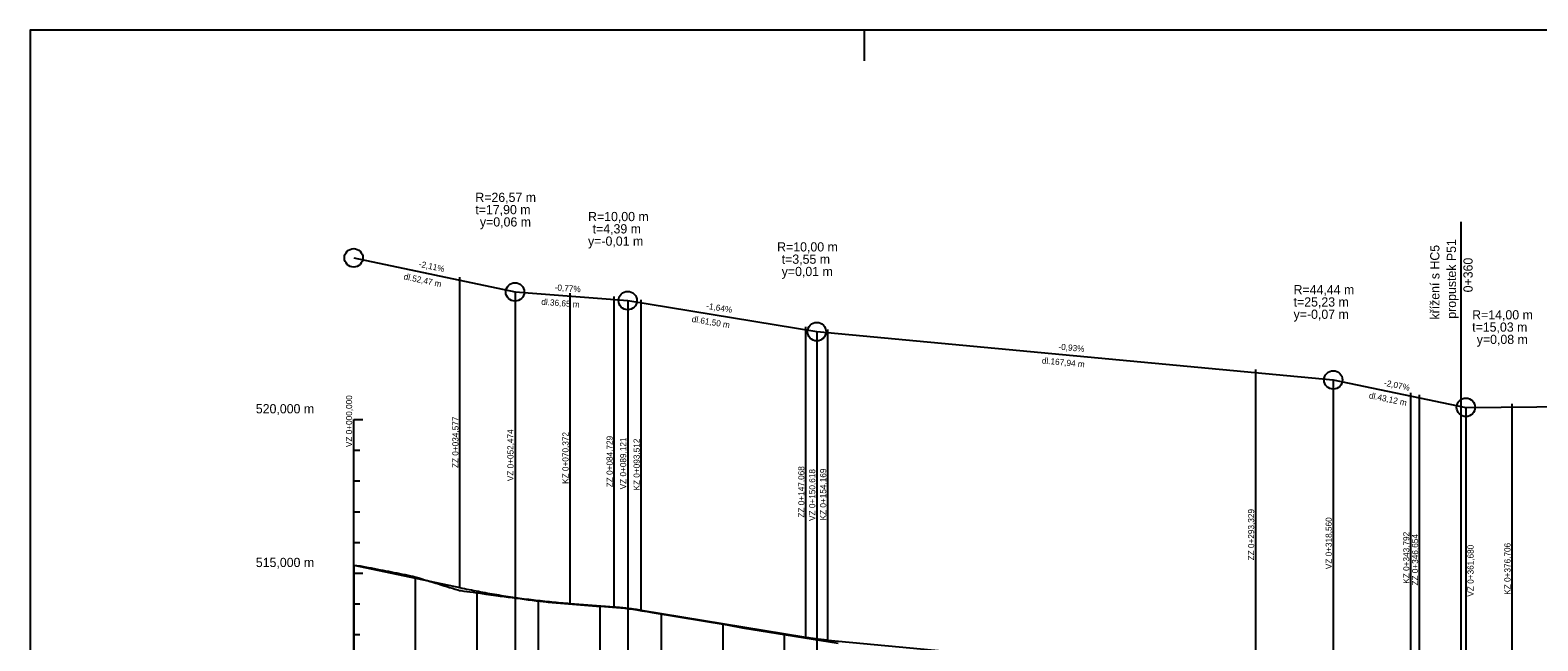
# Model space of a CAD drawing. Extents: x -632716 to -629545, y -1094726 to -1088285.
# Drawn here: x -632716 to -632225.7, y -1093293.8 to -1093095.1 of the extents above; entities that cross this region are included whole.
import ezdxf

# ---------------------------------------------------------------- set-up
doc = ezdxf.new("R2010")
doc.units = 0
for name, color, linetype in [('20', 7, 'Continuous'), ('Default', 7, 'Continuous'), ('formát', 7, 'Continuous'), ('REZ_POPIS', 7, 'Continuous'), ('REZ_TENKA', 7, 'Continuous'), ('REZ_TLUSTA', 7, 'Continuous'), ('SKLONY_NIVELETA', 7, 'Continuous'), ('SKLONY_POPIS', 7, 'Continuous'), ('TECNY_NIVELETA', 7, 'Continuous'), ('VOZOVKA', 7, 'Continuous')]:
    doc.layers.add(name, color=color, linetype=linetype)

msp = doc.modelspace()

# ---------------------------------------------------------------- linework, layer by layer
at = {"layer": '20'}
for points in [[(-632610.75, -1093269.14), (-632610.75, -1093521.74), (-632610.75, -1093571.74), (-632610.75, -1093511.74)], [(-632590.75, -1093273.37), (-632590.75, -1093521.74), (-632590.75, -1093571.74), (-632590.75, -1093511.74)], [(-632570.75, -1093277.54), (-632570.75, -1093521.74), (-632570.75, -1093571.74), (-632570.75, -1093511.74)], [(-632550.75, -1093280.6), (-632550.75, -1093521.74), (-632550.75, -1093571.74), (-632550.75, -1093511.74)], [(-632530.75, -1093282.34), (-632530.75, -1093521.74), (-632530.75, -1093571.74), (-632530.75, -1093511.74)], [(-632510.75, -1093284.83), (-632510.75, -1093521.74), (-632510.75, -1093571.74), (-632510.75, -1093511.74)], [(-632490.75, -1093288.12), (-632490.75, -1093521.74), (-632490.75, -1093571.74), (-632490.75, -1093511.74)], [(-632470.75, -1093291.41), (-632470.75, -1093521.74), (-632470.75, -1093571.74), (-632470.75, -1093511.74)]]:
    msp.add_lwpolyline(points, dxfattribs=at)
at = {"layer": 'Default'}
for p, q in [((-632610.75, -1093269.14), (-632576.18, -1093276.45)), ((-632610.75, -1093269.14), (-632576.18, -1093276.45)), ((-632540.38, -1093281.6), (-632526.02, -1093282.7)), ((-632540.38, -1093281.6), (-632526.02, -1093282.7)), ((-632517.24, -1093283.76), (-632463.69, -1093292.57)), ((-632517.24, -1093283.76), (-632463.69, -1093292.57)), ((-632456.58, -1093293.49), (-632317.42, -1093306.49)), ((-632456.58, -1093293.49), (-632317.42, -1093306.49))]:
    msp.add_line(p, q, dxfattribs=at)
for points in [[(-632576.18, -1093276.45), (-632575.43, -1093276.6), (-632574.69, -1093276.76), (-632573.94, -1093276.91), (-632573.19, -1093277.06), (-632572.45, -1093277.21), (-632571.7, -1093277.35), (-632570.96, -1093277.5), (-632570.21, -1093277.64), (-632569.46, -1093277.78), (-632568.72, -1093277.92), (-632567.97, -1093278.05), (-632567.23, -1093278.19), (-632566.48, -1093278.32), (-632565.74, -1093278.45), (-632564.99, -1093278.58), (-632564.24, -1093278.7), (-632563.5, -1093278.82), (-632562.75, -1093278.95), (-632562.01, -1093279.06), (-632561.26, -1093279.18), (-632560.52, -1093279.3), (-632559.77, -1093279.41), (-632559.02, -1093279.52), (-632557.53, -1093279.73), (-632556.79, -1093279.84), (-632556.04, -1093279.94), (-632555.3, -1093280.04), (-632554.55, -1093280.14), (-632553.8, -1093280.23), (-632553.06, -1093280.33), (-632552.31, -1093280.42), (-632551.57, -1093280.51), (-632550.82, -1093280.6), (-632550.08, -1093280.68), (-632549.33, -1093280.77), (-632548.58, -1093280.85), (-632547.84, -1093280.93), (-632547.09, -1093281), (-632546.35, -1093281.08), (-632545.6, -1093281.15), (-632544.86, -1093281.22), (-632544.11, -1093281.29), (-632543.36, -1093281.36), (-632542.62, -1093281.42), (-632541.87, -1093281.48), (-632541.13, -1093281.54), (-632540.38, -1093281.6)], [(-632576.18, -1093276.45), (-632575.43, -1093276.6), (-632574.69, -1093276.76), (-632573.94, -1093276.91), (-632573.19, -1093277.06), (-632572.45, -1093277.21), (-632571.7, -1093277.35), (-632570.96, -1093277.5), (-632570.21, -1093277.64), (-632569.46, -1093277.78), (-632568.72, -1093277.92), (-632567.97, -1093278.05), (-632567.23, -1093278.19), (-632566.48, -1093278.32), (-632565.74, -1093278.45), (-632564.99, -1093278.58), (-632564.24, -1093278.7), (-632563.5, -1093278.82), (-632562.75, -1093278.95), (-632562.01, -1093279.06), (-632561.26, -1093279.18), (-632560.52, -1093279.3), (-632559.77, -1093279.41), (-632559.02, -1093279.52), (-632557.53, -1093279.73), (-632556.79, -1093279.84), (-632556.04, -1093279.94), (-632555.3, -1093280.04), (-632554.55, -1093280.14), (-632553.8, -1093280.23), (-632553.06, -1093280.33), (-632552.31, -1093280.42), (-632551.57, -1093280.51), (-632550.82, -1093280.6), (-632550.08, -1093280.68), (-632549.33, -1093280.77), (-632548.58, -1093280.85), (-632547.84, -1093280.93), (-632547.09, -1093281), (-632546.35, -1093281.08), (-632545.6, -1093281.15), (-632544.86, -1093281.22), (-632544.11, -1093281.29), (-632543.36, -1093281.36), (-632542.62, -1093281.42), (-632541.87, -1093281.48), (-632541.13, -1093281.54), (-632540.38, -1093281.6)], [(-632526.02, -1093282.7), (-632525.84, -1093282.72), (-632525.66, -1093282.73), (-632525.48, -1093282.75), (-632525.29, -1093282.76), (-632525.11, -1093282.78), (-632524.93, -1093282.79), (-632524.74, -1093282.81), (-632524.56, -1093282.83), (-632524.38, -1093282.84), (-632524.19, -1093282.86), (-632524.01, -1093282.88), (-632523.83, -1093282.9), (-632523.65, -1093282.91), (-632523.46, -1093282.93), (-632523.28, -1093282.95), (-632523.1, -1093282.97), (-632522.91, -1093282.99), (-632522.73, -1093283.01), (-632522.55, -1093283.03), (-632522.36, -1093283.05), (-632522.18, -1093283.07), (-632522, -1093283.09), (-632521.82, -1093283.11), (-632521.45, -1093283.16), (-632521.27, -1093283.18), (-632521.08, -1093283.2), (-632520.9, -1093283.23), (-632520.72, -1093283.25), (-632520.54, -1093283.27), (-632520.35, -1093283.3), (-632520.17, -1093283.32), (-632519.99, -1093283.35), (-632519.8, -1093283.37), (-632519.62, -1093283.4), (-632519.44, -1093283.42), (-632519.25, -1093283.45), (-632519.07, -1093283.48), (-632518.89, -1093283.5), (-632518.71, -1093283.53), (-632518.52, -1093283.56), (-632518.34, -1093283.59), (-632518.16, -1093283.62), (-632517.97, -1093283.64), (-632517.79, -1093283.67), (-632517.61, -1093283.7), (-632517.42, -1093283.73), (-632517.24, -1093283.76)], [(-632526.02, -1093282.7), (-632525.84, -1093282.72), (-632525.66, -1093282.73), (-632525.48, -1093282.75), (-632525.29, -1093282.76), (-632525.11, -1093282.78), (-632524.93, -1093282.79), (-632524.74, -1093282.81), (-632524.56, -1093282.83), (-632524.38, -1093282.84), (-632524.19, -1093282.86), (-632524.01, -1093282.88), (-632523.83, -1093282.9), (-632523.65, -1093282.91), (-632523.46, -1093282.93), (-632523.28, -1093282.95), (-632523.1, -1093282.97), (-632522.91, -1093282.99), (-632522.73, -1093283.01), (-632522.55, -1093283.03), (-632522.36, -1093283.05), (-632522.18, -1093283.07), (-632522, -1093283.09), (-632521.82, -1093283.11), (-632521.45, -1093283.16), (-632521.27, -1093283.18), (-632521.08, -1093283.2), (-632520.9, -1093283.23), (-632520.72, -1093283.25), (-632520.54, -1093283.27), (-632520.35, -1093283.3), (-632520.17, -1093283.32), (-632519.99, -1093283.35), (-632519.8, -1093283.37), (-632519.62, -1093283.4), (-632519.44, -1093283.42), (-632519.25, -1093283.45), (-632519.07, -1093283.48), (-632518.89, -1093283.5), (-632518.71, -1093283.53), (-632518.52, -1093283.56), (-632518.34, -1093283.59), (-632518.16, -1093283.62), (-632517.97, -1093283.64), (-632517.79, -1093283.67), (-632517.61, -1093283.7), (-632517.42, -1093283.73), (-632517.24, -1093283.76)], [(-632463.69, -1093292.57), (-632463.54, -1093292.6), (-632463.39, -1093292.62), (-632463.24, -1093292.64), (-632463.09, -1093292.67), (-632462.95, -1093292.69), (-632462.8, -1093292.71), (-632462.65, -1093292.74), (-632462.5, -1093292.76), (-632462.35, -1093292.78), (-632462.21, -1093292.8), (-632462.06, -1093292.83), (-632461.91, -1093292.85), (-632461.76, -1093292.87), (-632461.61, -1093292.89), (-632461.47, -1093292.91), (-632461.32, -1093292.93), (-632461.17, -1093292.95), (-632461.02, -1093292.97), (-632460.87, -1093292.99), (-632460.73, -1093293.01), (-632460.58, -1093293.03), (-632460.43, -1093293.05), (-632460.28, -1093293.07), (-632459.99, -1093293.11), (-632459.84, -1093293.13), (-632459.69, -1093293.15), (-632459.54, -1093293.17), (-632459.4, -1093293.18), (-632459.25, -1093293.2), (-632459.1, -1093293.22), (-632458.95, -1093293.24), (-632458.8, -1093293.25), (-632458.66, -1093293.27), (-632458.51, -1093293.29), (-632458.36, -1093293.31), (-632458.21, -1093293.32), (-632458.06, -1093293.34), (-632457.92, -1093293.35), (-632457.77, -1093293.37), (-632457.62, -1093293.38), (-632457.47, -1093293.4), (-632457.32, -1093293.41), (-632457.18, -1093293.43), (-632457.03, -1093293.44), (-632456.88, -1093293.46), (-632456.73, -1093293.47), (-632456.58, -1093293.49)], [(-632463.69, -1093292.57), (-632463.54, -1093292.6), (-632463.39, -1093292.62), (-632463.24, -1093292.64), (-632463.09, -1093292.67), (-632462.95, -1093292.69), (-632462.8, -1093292.71), (-632462.65, -1093292.74), (-632462.5, -1093292.76), (-632462.35, -1093292.78), (-632462.21, -1093292.8), (-632462.06, -1093292.83), (-632461.91, -1093292.85), (-632461.76, -1093292.87), (-632461.61, -1093292.89), (-632461.47, -1093292.91), (-632461.32, -1093292.93), (-632461.17, -1093292.95), (-632461.02, -1093292.97), (-632460.87, -1093292.99), (-632460.73, -1093293.01), (-632460.58, -1093293.03), (-632460.43, -1093293.05), (-632460.28, -1093293.07), (-632459.99, -1093293.11), (-632459.84, -1093293.13), (-632459.69, -1093293.15), (-632459.54, -1093293.17), (-632459.4, -1093293.18), (-632459.25, -1093293.2), (-632459.1, -1093293.22), (-632458.95, -1093293.24), (-632458.8, -1093293.25), (-632458.66, -1093293.27), (-632458.51, -1093293.29), (-632458.36, -1093293.31), (-632458.21, -1093293.32), (-632458.06, -1093293.34), (-632457.92, -1093293.35), (-632457.77, -1093293.37), (-632457.62, -1093293.38), (-632457.47, -1093293.4), (-632457.32, -1093293.41), (-632457.18, -1093293.43), (-632457.03, -1093293.44), (-632456.88, -1093293.46), (-632456.73, -1093293.47), (-632456.58, -1093293.49)]]:
    msp.add_lwpolyline(points, dxfattribs=at)
at = {"layer": 'formát'}
msp.add_line((-632444.61, -1093105.05), (-632444.61, -1093095.05), dxfattribs=at)
msp.add_lwpolyline([(-632715.96, -1093689.05), (-630764.61, -1093689.05), (-630764.61, -1093095.05), (-632715.96, -1093095.05)], close=True, dxfattribs=at)
at = {"layer": 'REZ_TENKA'}
for p, q in [((-632610.75, -1093571.74), (-632610.75, -1093221.74)), ((-632610.75, -1093231.74), (-632608.75, -1093231.74)), ((-632610.75, -1093241.74), (-632608.75, -1093241.74)), ((-632610.75, -1093251.74), (-632608.75, -1093251.74)), ((-632610.75, -1093261.74), (-632608.75, -1093261.74)), ((-632610.75, -1093281.74), (-632608.75, -1093281.74)), ((-632610.75, -1093291.74), (-632608.75, -1093291.74))]:
    msp.add_line(p, q, dxfattribs=at)
at = {"layer": 'REZ_TLUSTA'}
for p, q in [((-632610.75, -1093221.74), (-632607.75, -1093221.74)), ((-632610.75, -1093221.74), (-632607.75, -1093221.74)), ((-632610.75, -1093271.74), (-632607.75, -1093271.74))]:
    msp.add_line(p, q, dxfattribs=at)
at = {"layer": 'SKLONY_NIVELETA'}
for p, q in [((-632250.75, -1093157.4), (-632250.75, -1093316.8)), ((-632610.75, -1093169.14), (-632610.75, -1093169.14)), ((-632610.75, -1093169.14), (-632558.28, -1093180.23)), ((-632558.28, -1093180.23), (-632558.28, -1093571.74)), ((-632558.28, -1093180.23), (-632521.63, -1093183.04)), ((-632521.63, -1093183.04), (-632521.63, -1093571.74)), ((-632521.63, -1093183.04), (-632460.14, -1093193.15)), ((-632460.14, -1093193.15), (-632460.14, -1093571.74)), ((-632460.14, -1093193.15), (-632292.19, -1093208.85)), ((-632292.19, -1093208.85), (-632292.19, -1093571.74)), ((-632292.19, -1093208.85), (-632249.07, -1093217.78)), ((-632249.07, -1093217.78), (-632179.54, -1093217.25)), ((-632249.07, -1093217.78), (-632249.07, -1093571.74)), ((-632610.75, -1093269.14), (-632576.18, -1093276.45)), ((-632540.38, -1093281.6), (-632526.02, -1093282.7)), ((-632517.24, -1093283.76), (-632463.69, -1093292.57)), ((-632456.58, -1093293.49), (-632317.42, -1093306.49))]:
    msp.add_line(p, q, dxfattribs=at)
for points in [[(-632576.18, -1093276.45), (-632575.43, -1093276.6), (-632574.69, -1093276.76), (-632573.94, -1093276.91), (-632573.19, -1093277.06), (-632572.45, -1093277.21), (-632571.7, -1093277.35), (-632570.96, -1093277.5), (-632570.21, -1093277.64), (-632569.46, -1093277.78), (-632568.72, -1093277.92), (-632567.97, -1093278.05), (-632567.23, -1093278.19), (-632566.48, -1093278.32), (-632565.74, -1093278.45), (-632564.99, -1093278.58), (-632564.24, -1093278.7), (-632563.5, -1093278.82), (-632562.75, -1093278.95), (-632562.01, -1093279.06), (-632561.26, -1093279.18), (-632560.52, -1093279.3), (-632559.77, -1093279.41), (-632559.02, -1093279.52), (-632557.53, -1093279.73), (-632556.79, -1093279.84), (-632556.04, -1093279.94), (-632555.3, -1093280.04), (-632554.55, -1093280.14), (-632553.8, -1093280.23), (-632553.06, -1093280.33), (-632552.31, -1093280.42), (-632551.57, -1093280.51), (-632550.82, -1093280.6), (-632550.08, -1093280.68), (-632549.33, -1093280.77), (-632548.58, -1093280.85), (-632547.84, -1093280.93), (-632547.09, -1093281), (-632546.35, -1093281.08), (-632545.6, -1093281.15), (-632544.86, -1093281.22), (-632544.11, -1093281.29), (-632543.36, -1093281.36), (-632542.62, -1093281.42), (-632541.87, -1093281.48), (-632541.13, -1093281.54), (-632540.38, -1093281.6)], [(-632526.02, -1093282.7), (-632525.84, -1093282.72), (-632525.66, -1093282.73), (-632525.48, -1093282.75), (-632525.29, -1093282.76), (-632525.11, -1093282.78), (-632524.93, -1093282.79), (-632524.74, -1093282.81), (-632524.56, -1093282.83), (-632524.38, -1093282.84), (-632524.19, -1093282.86), (-632524.01, -1093282.88), (-632523.83, -1093282.9), (-632523.65, -1093282.91), (-632523.46, -1093282.93), (-632523.28, -1093282.95), (-632523.1, -1093282.97), (-632522.91, -1093282.99), (-632522.73, -1093283.01), (-632522.55, -1093283.03), (-632522.36, -1093283.05), (-632522.18, -1093283.07), (-632522, -1093283.09), (-632521.82, -1093283.11), (-632521.45, -1093283.16), (-632521.27, -1093283.18), (-632521.08, -1093283.2), (-632520.9, -1093283.23), (-632520.72, -1093283.25), (-632520.54, -1093283.27), (-632520.35, -1093283.3), (-632520.17, -1093283.32), (-632519.99, -1093283.35), (-632519.8, -1093283.37), (-632519.62, -1093283.4), (-632519.44, -1093283.42), (-632519.25, -1093283.45), (-632519.07, -1093283.48), (-632518.89, -1093283.5), (-632518.71, -1093283.53), (-632518.52, -1093283.56), (-632518.34, -1093283.59), (-632518.16, -1093283.62), (-632517.97, -1093283.64), (-632517.79, -1093283.67), (-632517.61, -1093283.7), (-632517.42, -1093283.73), (-632517.24, -1093283.76)], [(-632463.69, -1093292.57), (-632463.54, -1093292.6), (-632463.39, -1093292.62), (-632463.24, -1093292.64), (-632463.09, -1093292.67), (-632462.95, -1093292.69), (-632462.8, -1093292.71), (-632462.65, -1093292.74), (-632462.5, -1093292.76), (-632462.35, -1093292.78), (-632462.21, -1093292.8), (-632462.06, -1093292.83), (-632461.91, -1093292.85), (-632461.76, -1093292.87), (-632461.61, -1093292.89), (-632461.47, -1093292.91), (-632461.32, -1093292.93), (-632461.17, -1093292.95), (-632461.02, -1093292.97), (-632460.87, -1093292.99), (-632460.73, -1093293.01), (-632460.58, -1093293.03), (-632460.43, -1093293.05), (-632460.28, -1093293.07), (-632459.99, -1093293.11), (-632459.84, -1093293.13), (-632459.69, -1093293.15), (-632459.54, -1093293.17), (-632459.4, -1093293.18), (-632459.25, -1093293.2), (-632459.1, -1093293.22), (-632458.95, -1093293.24), (-632458.8, -1093293.25), (-632458.66, -1093293.27), (-632458.51, -1093293.29), (-632458.36, -1093293.31), (-632458.21, -1093293.32), (-632458.06, -1093293.34), (-632457.92, -1093293.35), (-632457.77, -1093293.37), (-632457.62, -1093293.38), (-632457.47, -1093293.4), (-632457.32, -1093293.41), (-632457.18, -1093293.43), (-632457.03, -1093293.44), (-632456.88, -1093293.46), (-632456.73, -1093293.47), (-632456.58, -1093293.49)]]:
    msp.add_lwpolyline(points, dxfattribs=at)
for centre in [(-632610.75, -1093169.14), (-632558.28, -1093180.23), (-632521.63, -1093183.04), (-632460.14, -1093193.15), (-632292.19, -1093208.85), (-632249.07, -1093217.78)]:
    msp.add_circle(centre, 3, dxfattribs=at)
at = {"layer": 'TECNY_NIVELETA'}
for p, q in [((-632610.75, -1093169.14), (-632610.75, -1093169.14)), ((-632576.18, -1093276.45), (-632576.18, -1093175.45)), ((-632558.28, -1093180.23), (-632558.28, -1093180.23)), ((-632540.38, -1093281.6), (-632540.38, -1093180.6)), ((-632526.02, -1093282.7), (-632526.02, -1093181.7)), ((-632521.63, -1093183.04), (-632521.63, -1093183.04)), ((-632517.24, -1093283.76), (-632517.24, -1093182.76)), ((-632463.69, -1093292.57), (-632463.69, -1093191.57)), ((-632460.14, -1093193.15), (-632460.14, -1093193.15)), ((-632456.58, -1093293.49), (-632456.58, -1093192.49)), ((-632317.42, -1093306.49), (-632317.42, -1093205.49)), ((-632292.19, -1093208.85), (-632292.19, -1093208.85)), ((-632266.96, -1093314.08), (-632266.96, -1093213.08)), ((-632264.1, -1093314.67), (-632264.1, -1093213.67)), ((-632249.07, -1093217.78), (-632249.07, -1093217.78)), ((-632234.05, -1093317.67), (-632234.05, -1093216.67))]:
    msp.add_line(p, q, dxfattribs=at)
at = {"layer": 'VOZOVKA'}
msp.add_lwpolyline([(-632610.75, -1093269.14), (-632610.68, -1093269.16), (-632608.61, -1093269.35), (-632608.09, -1093269.45), (-632607.09, -1093269.65), (-632606.09, -1093269.84), (-632605.09, -1093270.03), (-632604.09, -1093270.23), (-632603.09, -1093270.42), (-632602.18, -1093270.6), (-632601.28, -1093270.78), (-632600.37, -1093270.96), (-632599.47, -1093271.13), (-632598.56, -1093271.31), (-632597.66, -1093271.49), (-632596.75, -1093271.67), (-632595.84, -1093271.85), (-632594.94, -1093272.03), (-632594.03, -1093272.21), (-632593.13, -1093272.39), (-632592.22, -1093272.57), (-632591.32, -1093272.75), (-632591.23, -1093272.77), (-632590.41, -1093273.02), (-632589.51, -1093273.3), (-632588.6, -1093273.58), (-632587.7, -1093273.86), (-632586.79, -1093274.14), (-632585.89, -1093274.42), (-632584.98, -1093274.7), (-632584.08, -1093274.98), (-632583.17, -1093275.25), (-632582.26, -1093275.53), (-632581.36, -1093275.81), (-632580.45, -1093276.09), (-632580.42, -1093276.1), (-632579.55, -1093276.37), (-632578.64, -1093276.65), (-632577.74, -1093276.92), (-632576.83, -1093277.2), (-632576.37, -1093277.34), (-632575.93, -1093277.4), (-632574.93, -1093277.54), (-632573.93, -1093277.67), (-632572.93, -1093277.81), (-632571.93, -1093277.95), (-632570.93, -1093278.09), (-632569.47, -1093278.29), (-632567.8, -1093278.53), (-632566.13, -1093278.76), (-632564.47, -1093278.99), (-632563.16, -1093279.17), (-632561.85, -1093279.34), (-632560.54, -1093279.52), (-632559.23, -1093279.69), (-632557.93, -1093279.86), (-632556.62, -1093280.03), (-632555.31, -1093280.2), (-632554, -1093280.36), (-632553.8, -1093280.39), (-632552.69, -1093280.52), (-632551.39, -1093280.69), (-632550.08, -1093280.85), (-632549.17, -1093280.96), (-632548.77, -1093281), (-632547.46, -1093281.12), (-632546.15, -1093281.24), (-632544.85, -1093281.36), (-632543.54, -1093281.48), (-632542.23, -1093281.59), (-632540.92, -1093281.7), (-632539.61, -1093281.81), (-632538.31, -1093281.92), (-632537, -1093282.02), (-632535.69, -1093282.13), (-632534.38, -1093282.23), (-632533.07, -1093282.32), (-632531.77, -1093282.42), (-632530.46, -1093282.51), (-632529.15, -1093282.6), (-632527.84, -1093282.69), (-632526.53, -1093282.78), (-632525.23, -1093282.86), (-632524.94, -1093282.88), (-632523.92, -1093283), (-632522.61, -1093283.15), (-632521.3, -1093283.29), (-632520.56, -1093283.38), (-632519.99, -1093283.47), (-632518.69, -1093283.69), (-632517.02, -1093283.97), (-632515.35, -1093284.25), (-632513.69, -1093284.52), (-632489.3, -1093288.56), (-632484.36, -1093289.51), (-632453.2, -1093294.51)], dxfattribs=at)

# ---------------------------------------------------------------- texts
at = {"layer": 'REZ_POPIS'}
for s, p in [('520,000 m', (-632642.57, -1093219.74)), ('520,000 m', (-632642.57, -1093219.74)), ('515,000 m', (-632642.57, -1093269.74))]:
    msp.add_text(s, height=3, dxfattribs=at).set_placement(p)
at = {"layer": 'SKLONY_POPIS'}
for s, p in [('R=26,57 m', (-632571.19, -1093150.95)), ('t=17,90 m', (-632571.19, -1093154.95)), ('R=10,00 m', (-632534.54, -1093157.2)), ('y=0,06 m', (-632569.7, -1093158.95)), ('t=4,39 m', (-632533.05, -1093161.2)), ('y=-0,01 m', (-632534.54, -1093165.2)), ('R=10,00 m', (-632473.04, -1093167.07)), ('t=3,55 m', (-632471.56, -1093171.07)), ('y=0,01 m', (-632471.56, -1093175.07)), ('R=44,44 m', (-632305.1, -1093180.99)), ('t=25,23 m', (-632305.1, -1093184.99)), ('y=-0,07 m', (-632305.1, -1093188.99)), ('R=14,00 m', (-632247.03, -1093189.17)), ('t=15,03 m', (-632247.03, -1093193.17)), ('y=0,08 m', (-632245.54, -1093197.17))]:
    msp.add_text(s, height=3, dxfattribs=at).set_placement(p)
for s, height, rotation, p in [('propustek P51', 3, 90, (-632252.27, -1093188.94)), ('křížení s HC5', 3, 90, (-632257.67, -1093189.23)), ('0+360', 3, 90, (-632246.87, -1093180.37)), ('dl.52,47 m', 2, 348.064, (-632594.63, -1093176.12)), ('-2,11%', 2, 348.064, (-632589.71, -1093172.05)), ('-0,77%', 2, 355.6163, (-632545.45, -1093179.71)), ('dl.36,65 m', 2, 355.6163, (-632549.79, -1093184.39)), ('-1,64%', 2, 350.6593, (-632496.2, -1093185.7)), ('dl.61,50 m', 2, 350.6593, (-632500.92, -1093189.99)), ('-0,93%', 2, 354.6597, (-632381.63, -1093198.99)), ('dl.167,94 m', 2, 354.6597, (-632387.03, -1093203.5)), ('dl.43,12 m', 2, 348.3039, (-632280.74, -1093214.8)), ('-2,07%', 2, 348.3039, (-632275.84, -1093210.71)), ('VZ 0+000,000', 2, 90, (-632611.25, -1093230.72)), ('ZZ 0+034,577', 2, 90, (-632576.68, -1093237.53)), ('VZ 0+052,474', 2, 90, (-632558.78, -1093241.81)), ('KZ 0+070,372', 2, 90, (-632540.88, -1093242.68)), ('ZZ 0+084,729', 2, 90, (-632526.52, -1093243.78)), ('VZ 0+089,121', 2, 90, (-632522.13, -1093244.46)), ('KZ 0+093,512', 2, 90, (-632517.74, -1093244.84)), ('ZZ 0+147,068', 2, 90, (-632464.19, -1093253.65)), ('VZ 0+150,618', 2, 90, (-632460.64, -1093254.74)), ('KZ 0+154,169', 2, 90, (-632457.08, -1093254.57)), ('ZZ 0+293,329', 2, 90, (-632317.92, -1093267.58)), ('VZ 0+318,560', 2, 90, (-632292.69, -1093270.44)), ('KZ 0+343,792', 2, 90, (-632267.46, -1093275.16)), ('ZZ 0+346,654', 2, 90, (-632264.6, -1093275.75)), ('VZ 0+361,680', 2, 90, (-632246.56, -1093279.36)), ('KZ 0+376,706', 2, 90, (-632234.55, -1093278.75))]:
    msp.add_text(s, height=height, rotation=rotation, dxfattribs=at).set_placement(p)

doc.saveas('drawing.dxf')
